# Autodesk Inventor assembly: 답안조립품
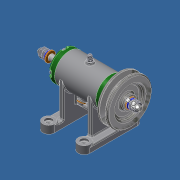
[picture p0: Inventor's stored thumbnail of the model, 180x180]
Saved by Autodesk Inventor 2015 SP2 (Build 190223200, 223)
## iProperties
Created: 2015-11
Part Number: 답안조립품
Document SubType Name: Assembly
Designer: AMC
Author: AMC
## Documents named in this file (15)
- C:\Users\AMC\Desktop\451109V1029\답안조립품.iam
- C:\Users\AMC\Desktop\451109V1029\본체.ipt
- C:\Users\AMC\Desktop\451109V1029\축.ipt
- C:\Users\AMC\Desktop\451109V1029\베어링 15 x 32 x 9.ipt
- C:\Users\AMC\Desktop\451109V1029\커버.ipt
- C:\Users\AMC\Desktop\451109V1029\오일 실 15 25 7.ipt
- C:\Users\AMC\Desktop\451109V1029\키 3 x 3 x 12.ipt
- C:\Users\AMC\Desktop\451109V1029\V벨트풀리.ipt
- C:\Users\AMC\Desktop\451109V1029\스퍼기어.ipt
- C:\Users\AMC\Desktop\451109V1029\와셔 8x17.ipt
- C:\Users\AMC\Desktop\451109V1029\스프링와셔 8.ipt
- C:\Users\AMC\Desktop\451109V1029\너트 M 8.ipt
- C:\Users\AMC\Desktop\451109V1029\볼트 M4 x 12.ipt
- C:\Users\AMC\Desktop\451109V1029\니플 M 6 x 0.75.ipt
- C:\Users\AMC\Desktop\451109V1029\와셔 6x11.5.ipt
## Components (12 placed, 3 different names)
1. KS B 2023 6002 - 15 x 32 x 9:1
2. KS B 2023 6002 - 15 x 32 x 9:2
3. V벨트풀리:1 — 각도:3
4. ISO 4762 M4 x 12:5
5. ISO 4762 M4 x 12:6
6. ISO 4762 M4 x 12:7
7. ISO 4762 M4 x 12:8
8. ISO 4762 M4 x 12:9
9. ISO 4762 M4 x 12:1
10. ISO 4762 M4 x 12:2
11. ISO 4762 M4 x 12:3
12. ISO 4762 M4 x 12:4
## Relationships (1: Angle 1)
- 각도:3 [Angle]: V벨트풀리:1
